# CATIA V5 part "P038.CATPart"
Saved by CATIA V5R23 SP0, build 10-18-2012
Part number: P038
Definition: Entretoise levier
Description: Entretoise levier
Bounding box of the stored display mesh (mm): x -6 to 6, y -17 to 17, z -5.956 to 5.956
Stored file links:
  C:\wamp\www\COURS\CONCEPTION GMP1\TITRE 02-SEMESTRE 2\03-TP7-PRESSE MECANIQUE\eleve\P038.CATPart
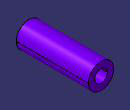
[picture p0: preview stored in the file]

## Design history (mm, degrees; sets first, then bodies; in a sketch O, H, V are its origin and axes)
Body1 (main body)
  Sketch1 on zx-plane, origin (0, 0, 0), H (-1, 0, 0), V (0, 0, 1)
    circle A1 centre (0, 0) radius 6
    circle A2 centre (0, 0) radius 3
    radius A1 = 6
    radius A2 = 3
  Pad1: profile Sketch1, direction (0, 1, 0), length 17, mirrored extent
